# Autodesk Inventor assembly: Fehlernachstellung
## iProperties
Created: 2008-06
Part Number: Fehlernachstellung
Document SubType Name: Assembly
Designer: Goedde
Mass: 28639.1 g
Surface Area: 3520.22 cm^2
Volume: 3643.7 cm^3
Density: 7.85989 g/cm^3
Author: Goedde
